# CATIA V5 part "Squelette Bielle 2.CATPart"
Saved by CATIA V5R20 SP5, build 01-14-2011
Part number: Squelette Bielle 2
Publications: "Droite.1", "Droite.2", "Droite.3"
Bounding box of the stored display mesh (mm): x -100 to -100, y -250 to -50, z -30 to 30
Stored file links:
  U:\CFAO\Thinkmotion\Squelette Bielle 2.CATPart
  U:\CFAO\Thinkmotion\Bras Articule.CATProduct
  U:\CFAO\Thinkmotion\Squelette general.CATPart
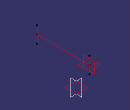
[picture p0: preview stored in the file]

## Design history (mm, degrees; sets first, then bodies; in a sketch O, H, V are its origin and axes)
Parameters
  Decalage = 20 mm
Set1
  Line1: type PtPt, FirstPoint Point1, SecondPoint Point2
  Line2: type Normal, RefPoint Point1, RefSkin Plane3, Start -30, End 30
  Line3: type Normal, RefPoint Point2, RefSkin Plane3, Start -30, End 30
  Plane1: type OffsetPt, RefPlane xy-plane, RefPoint Point1
  Plane2: type OffsetPt, RefPlane yz-plane, RefPoint Point1
Set2
  Point1: linked copy from another document
  Point2: linked copy from another document
  Plane3 "Plan reference 1": linked copy from another document
Body1 (main body)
